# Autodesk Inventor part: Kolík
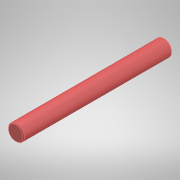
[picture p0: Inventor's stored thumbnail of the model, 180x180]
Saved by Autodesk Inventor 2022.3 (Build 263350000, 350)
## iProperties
Created: 2025-11
Part Number: Kolík
Material: Všeobecné
Document SubType Name: Modeling
Designer: Hra42
Density: 1 g/cm^3
Appearance: Výchozí
Author: Hra42
Sending System: SolidWorks 2012
Last Author: Hra42
Last Saved: 2025-11-10
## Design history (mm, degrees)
node "Kolík.SLDPRT"
node "Těleso1"
feature "Zkosení1"
